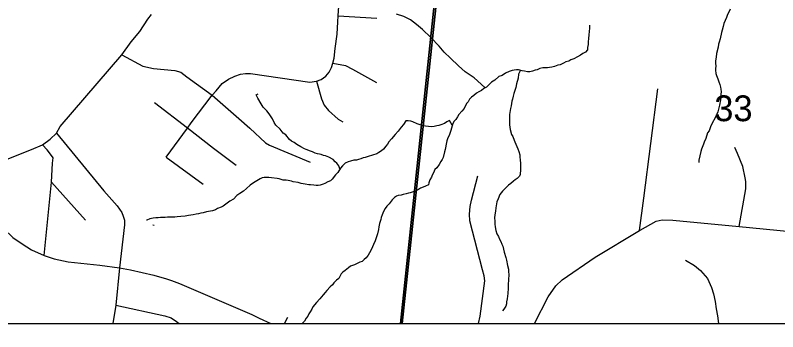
# Model space of a CAD drawing. Extents: x -8.2 to 38.5, y -0.1 to 21.9.
# Drawn here: x 3.122 to 4.362, y 17.376 to 17.891 of the extents above; entities that cross this region are included whole.
import ezdxf

# ---------------------------------------------------------------- set-up
doc = ezdxf.new("R2010")
doc.units = 0
for name, color, linetype in [('Default', 7, 'Continuous'), ('GM_X_Adjacent_County', 7, 'Continuous'), ('GM_X_Adjacent_County_Text', 7, 'Continuous'), ('GM_X_County_Road_Text', 7, 'Continuous'), ('GM_X_Minor_River', 7, 'Continuous'), ('GM_X_Township_Subdivision_Text', 7, 'Continuous'), ('GM_X_Township_Text', 7, 'Continuous')]:
    doc.layers.add(name, color=color, linetype=linetype)

msp = doc.modelspace()

# ---------------------------------------------------------------- linework, layer by layer
at = {"layer": 'Default'}
for points in [[(3.7486, 17.3899), (3.8184, 18.0516), (3.8435, 18.2895), (3.8449, 18.303), (3.8472, 18.3279), (3.8854, 18.7517), (3.9289, 19.2353), (3.9436, 19.3979), (3.9961, 19.9817), (4.0302, 20.3597), (4.0404, 20.4649), (4.0467, 20.5533), (4.0665, 20.7635), (4.0666, 20.7645), (2.1634, 20.7645), (2.1634, 15.4317)], [(8.9634, 15.3136), (8.9634, 20.7535), (8.8842, 20.7645), (4.0666, 20.7645), (4.0665, 20.7635), (4.0467, 20.5533), (4.0404, 20.4649), (4.0302, 20.3597), (3.9961, 19.9817), (3.9436, 19.3979), (3.9289, 19.2353), (3.8854, 18.7517), (3.8472, 18.3279), (3.8449, 18.303), (3.8435, 18.2895), (3.8184, 18.0516), (3.7486, 17.3899)]]:
    msp.add_lwpolyline(points, dxfattribs=at)
at = {"layer": 'GM_X_Adjacent_County'}
msp.add_lwpolyline([(2.2499, 17.3899), (5.0356, 17.3899), (5.0356, 16.67), (2.2499, 16.67)], close=True, dxfattribs=at)
at = {"layer": 'GM_X_Adjacent_County_Text'}
for points in [[(2.8722, 17.3899), (2.7354, 17.4046), (2.8373, 18.4024), (3.8483, 18.3005), (3.7513, 17.3899)], [(3.7513, 17.3899), (3.8483, 18.3005), (4.8395, 18.1926), (4.7544, 17.3899)]]:
    msp.add_lwpolyline(points, dxfattribs=at)
at = {"layer": 'GM_X_Minor_River'}
for points in [[(4.2846, 17.9006), (4.2798, 17.8904), (4.2785, 17.887), (4.2745, 17.8772), (4.2732, 17.8723), (4.2719, 17.8667), (4.2706, 17.8625), (4.2685, 17.8523), (4.2668, 17.847), (4.2659, 17.8436), (4.265, 17.8387), (4.2625, 17.8288), (4.2619, 17.8224), (4.261, 17.8167), (4.2609, 17.8129), (4.2612, 17.8079), (4.2607, 17.8045), (4.261, 17.8015), (4.2616, 17.7961), (4.2627, 17.7926), (4.2644, 17.7873), (4.2662, 17.7826), (4.268, 17.7784), (4.269, 17.7738), (4.2697, 17.7704), (4.2699, 17.7665), (4.2695, 17.7627), (4.2693, 17.7567), (4.2688, 17.7532), (4.2674, 17.7445), (4.2645, 17.7336), (4.2608, 17.7249), (4.2548, 17.7144), (4.2528, 17.7095), (4.2503, 17.7031), (4.2476, 17.6998), (4.2451, 17.6903), (4.2422, 17.6843), (4.2414, 17.6813), (4.2381, 17.6734), (4.2369, 17.6696), (4.2352, 17.6624), (4.2338, 17.6552), (4.2335, 17.6513)], [(3.8859, 17.7726), (3.8795, 17.7789), (3.868, 17.7891), (3.8537, 17.7986), (3.843, 17.8087), (3.8296, 17.8209), (3.8196, 17.8306), (3.8114, 17.8403), (3.7977, 17.8547), (3.784, 17.8676), (3.7743, 17.8758), (3.7646, 17.8833), (3.7537, 17.8889), (3.742, 17.8926)], [(4.0561, 17.8746), (4.0556, 17.8693), (4.0551, 17.8651), (4.0549, 17.8582), (4.0544, 17.8533), (4.0538, 17.8472), (4.0537, 17.8434), (4.0528, 17.8381), (4.0524, 17.8347), (4.0492, 17.831), (4.045, 17.8284), (4.0411, 17.8259), (4.0365, 17.8233), (4.0303, 17.8197), (4.0257, 17.8183), (4.0222, 17.8161), (4.0176, 17.8151), (4.0134, 17.8129), (4.0084, 17.8104), (4.0045, 17.8094), (3.9992, 17.8076), (3.9946, 17.8062), (3.9907, 17.8056), (3.9873, 17.8053), (3.9839, 17.8054), (3.9801, 17.8051), (3.9751, 17.8041), (3.9705, 17.8023), (3.9674, 17.8013), (3.9632, 17.7999), (3.9586, 17.7988), (3.9552, 17.7986), (3.9499, 17.7998), (3.9465, 17.8007), (3.9404, 17.802), (3.937, 17.8021), (3.9332, 17.8018), (3.9301, 17.8008), (3.9252, 17.7994), (3.9194, 17.7969), (3.9136, 17.7929), (3.9086, 17.7911), (3.902, 17.7852), (3.8965, 17.7819), (3.8884, 17.7741), (3.8841, 17.7716), (3.8802, 17.7683), (3.8756, 17.7665), (3.8721, 17.7639), (3.8678, 17.7606), (3.8639, 17.7577), (3.8608, 17.7543), (3.8584, 17.7502), (3.8557, 17.7472), (3.852, 17.7394), (3.8481, 17.7349), (3.8434, 17.7293), (3.8414, 17.7256), (3.8386, 17.7211), (3.8355, 17.7189), (3.8335, 17.7147), (3.8302, 17.7034), (3.8277, 17.6955), (3.8256, 17.6913), (3.824, 17.6868), (3.8235, 17.6838), (3.8209, 17.6724), (3.8201, 17.669), (3.8176, 17.6596), (3.8163, 17.6566), (3.8143, 17.6532), (3.8116, 17.6483), (3.8076, 17.6427), (3.8045, 17.6401), (3.802, 17.6345), (3.8, 17.6307), (3.7988, 17.6277), (3.7964, 17.6232), (3.7944, 17.6183), (3.7939, 17.6153), (3.7889, 17.6131), (3.7855, 17.6113), (3.7812, 17.6099), (3.7762, 17.6066), (3.7704, 17.6041), (3.7643, 17.6024), (3.7612, 17.6017), (3.7574, 17.6007), (3.7528, 17.5993), (3.7494, 17.5986), (3.7448, 17.598), (3.7417, 17.5966), (3.7386, 17.5947), (3.7347, 17.591), (3.73, 17.5843), (3.7261, 17.5806), (3.7237, 17.5769), (3.7209, 17.5716), (3.7184, 17.5664), (3.7168, 17.5622), (3.7163, 17.5588)], [(3.9435, 17.8015), (3.9402, 17.7948), (3.9397, 17.7887), (3.9372, 17.7792), (3.9359, 17.7736), (3.9326, 17.7634), (3.9317, 17.7592), (3.9308, 17.7543), (3.9296, 17.7513), (3.9286, 17.7437), (3.9273, 17.7392), (3.9259, 17.7297), (3.9257, 17.7202), (3.9259, 17.7125), (3.9265, 17.7091), (3.9268, 17.7049), (3.9292, 17.6968), (3.931, 17.6937), (3.9335, 17.6879), (3.9346, 17.6849), (3.936, 17.6814), (3.9378, 17.6775), (3.9393, 17.6737), (3.9407, 17.6695), (3.9424, 17.6637), (3.9427, 17.6603), (3.9429, 17.6557), (3.9435, 17.6496), (3.9438, 17.6458), (3.9437, 17.6401), (3.9431, 17.6321), (3.9422, 17.6291), (3.9383, 17.6254), (3.9352, 17.6235), (3.9321, 17.6213), (3.9278, 17.6173), (3.9243, 17.6147), (3.9181, 17.6088), (3.9146, 17.6047), (3.9099, 17.5995), (3.9074, 17.5927), (3.9054, 17.5874), (3.9036, 17.578), (3.9027, 17.5726), (3.9021, 17.5662), (3.9016, 17.5613), (3.9018, 17.5563), (3.9017, 17.5513), (3.9023, 17.5468), (3.9037, 17.541), (3.9051, 17.5356), (3.9076, 17.531), (3.9094, 17.5271), (3.9116, 17.5229), (3.9134, 17.5187), (3.9148, 17.5156), (3.9172, 17.5056), (3.9196, 17.4971), (3.9207, 17.4925), (3.9223, 17.4841), (3.9241, 17.478), (3.9243, 17.473), (3.9246, 17.47), (3.9243, 17.4601), (3.9238, 17.4536), (3.9236, 17.4471), (3.923, 17.4384), (3.922, 17.4297), (3.9211, 17.4251), (3.9206, 17.4217), (3.9198, 17.4179), (3.9166, 17.4131), (3.9142, 17.4103)], [(3.65, 17.641), (3.648, 17.646), (3.645, 17.6503), (3.6421, 17.6527), (3.6387, 17.6562), (3.6316, 17.6602), (3.6264, 17.6622), (3.6233, 17.6631), (3.6196, 17.6643), (3.6165, 17.6648), (3.6135, 17.6656), (3.6097, 17.6665), (3.6052, 17.6689), (3.6018, 17.6698), (3.5951, 17.6726), (3.5921, 17.6739), (3.5861, 17.6767), (3.5797, 17.6807), (3.5756, 17.6838), (3.5711, 17.6863), (3.5678, 17.689), (3.5619, 17.6964), (3.5574, 17.6992), (3.5526, 17.7054), (3.5456, 17.7121), (3.543, 17.7167), (3.5401, 17.7222), (3.5347, 17.7307), (3.531, 17.7354), (3.5276, 17.7385), (3.5251, 17.7416), (3.5218, 17.7467), (3.5163, 17.756), (3.5134, 17.7614), (3.5169, 17.7632)], [(3.8327, 17.712), (3.8279, 17.7195), (3.8237, 17.7177), (3.8202, 17.7147), (3.8141, 17.7126), (3.8106, 17.7116), (3.8075, 17.7109), (3.8033, 17.7099), (3.7984, 17.7092), (3.7847, 17.7111), (3.7787, 17.7132), (3.7757, 17.7141), (3.7685, 17.7173), (3.7652, 17.7185), (3.761, 17.7194), (3.7572, 17.7191), (3.7532, 17.7135), (3.7493, 17.7087), (3.7446, 17.7024), (3.7395, 17.6968), (3.734, 17.6901), (3.7293, 17.6853), (3.7273, 17.6811), (3.7245, 17.6782), (3.7206, 17.6729), (3.7175, 17.6704), (3.7132, 17.6678), (3.7097, 17.6656), (3.7028, 17.6632), (3.6959, 17.6611), (3.6909, 17.6597), (3.6879, 17.659), (3.684, 17.6572), (3.6802, 17.6566), (3.6771, 17.6555), (3.6726, 17.6552), (3.6672, 17.6535), (3.6634, 17.6524), (3.6584, 17.6503), (3.654, 17.6459), (3.6509, 17.6425), (3.6465, 17.6354), (3.6426, 17.6317), (3.6375, 17.6242), (3.6344, 17.6216), (3.6305, 17.6199), (3.6255, 17.6173), (3.6224, 17.6163), (3.6175, 17.6149), (3.6144, 17.6142), (3.611, 17.6139), (3.6072, 17.6144), (3.6023, 17.6153), (3.5992, 17.6154), (3.5935, 17.6163), (3.5871, 17.6176), (3.5818, 17.6189), (3.5739, 17.6203), (3.5709, 17.6211), (3.5656, 17.622), (3.5625, 17.6225), (3.5576, 17.623), (3.5512, 17.6247), (3.5478, 17.6256), (3.5387, 17.6266), (3.5345, 17.6271), (3.5307, 17.6272), (3.5265, 17.6269), (3.5235, 17.6263), (3.5204, 17.6252), (3.5173, 17.6234), (3.5123, 17.6201), (3.5092, 17.6183), (3.5041, 17.6146), (3.4979, 17.6091), (3.4928, 17.605), (3.487, 17.601), (3.4824, 17.5977), (3.4769, 17.5921), (3.4707, 17.5885), (3.4599, 17.5804), (3.4568, 17.579), (3.451, 17.5765), (3.4475, 17.5747), (3.4425, 17.5729), (3.433, 17.5713), (3.4272, 17.5695), (3.4234, 17.5689), (3.4196, 17.5679), (3.4162, 17.5676), (3.4112, 17.5666), (3.4036, 17.5656), (3.3982, 17.5643), (3.391, 17.5637), (3.3849, 17.5631), (3.3814, 17.5628), (3.3772, 17.5626), (3.3734, 17.5627), (3.3692, 17.5624), (3.3654, 17.5621), (3.3613, 17.5622)], [(3.3613, 17.5622), (3.3578, 17.562), (3.354, 17.5617), (3.3506, 17.5614), (3.346, 17.5611), (3.3406, 17.5598), (3.3357, 17.558), (3.3353, 17.5579)], [(3.7163, 17.5588), (3.7143, 17.5524), (3.7134, 17.5471), (3.7125, 17.5425), (3.7108, 17.5357), (3.7095, 17.5308), (3.7074, 17.5244), (3.7046, 17.5184), (3.701, 17.5105), (3.6981, 17.5045), (3.6958, 17.5007), (3.6926, 17.4966), (3.6891, 17.4941), (3.686, 17.4907), (3.6821, 17.4893), (3.6737, 17.4853), (3.6702, 17.4839), (3.6671, 17.4832), (3.6636, 17.4803), (3.6586, 17.4762), (3.6547, 17.4733), (3.652, 17.4703), (3.648, 17.4632), (3.6441, 17.4603), (3.6402, 17.4558), (3.6378, 17.4528), (3.6343, 17.4495), (3.6288, 17.4436), (3.626, 17.4402), (3.6225, 17.4365), (3.6201, 17.4331), (3.617, 17.4298), (3.6119, 17.4242), (3.606, 17.4168), (3.6044, 17.4134), (3.6016, 17.4089), (3.5996, 17.4055), (3.5976, 17.4018), (3.5949, 17.3984), (3.5921, 17.3939), (3.5889, 17.3902), (3.5883, 17.3899)], [(3.3454, 17.5501), (3.3476, 17.5497)], [(4.2119, 17.4928), (4.2265, 17.4841), (4.2365, 17.4758), (4.248, 17.463), (4.2545, 17.4484), (4.2576, 17.4381), (4.2604, 17.4258), (4.262, 17.4136), (4.264, 17.4025), (4.2659, 17.3899)]]:
    msp.add_lwpolyline(points, dxfattribs=at)
at = {"layer": 'GM_X_Township_Subdivision_Text'}
for p, q in [((3.6471, 17.8897), (3.71, 17.886)), ((3.367, 17.6599), (3.4272, 17.6161)), ((3.181, 17.6197), (3.2362, 17.558)), ((3.5598, 17.3899), (3.5654, 17.3999))]:
    msp.add_line(p, q, dxfattribs=at)
for points in [[(3.6463, 17.8799), (3.6471, 17.8897), (3.6502, 17.9373), (3.6551, 18.0086)], [(3.367, 17.6599), (3.4018, 17.7072), (3.4079, 17.7157), (3.4422, 17.761), (3.4484, 17.7678), (3.4585, 17.78), (3.4685, 17.787), (3.479, 17.792), (3.4881, 17.795), (3.4963, 17.7959), (3.5046, 17.7961), (3.6012, 17.7819), (3.6119, 17.7835), (3.6195, 17.7866), (3.6268, 17.7919), (3.6323, 17.7984), (3.6364, 17.8059), (3.6385, 17.813), (3.6403, 17.8208), (3.6419, 17.8367), (3.6456, 17.8602), (3.6463, 17.8799)], [(3.2952, 17.8264), (3.3292, 17.8082), (3.3464, 17.8045), (3.3811, 17.8012), (3.3913, 17.7982), (3.4008, 17.7908), (3.4422, 17.761), (3.4855, 17.7228), (3.5032, 17.7071), (3.5286, 17.6835), (3.5355, 17.6797), (3.6014, 17.6521)], [(3.6385, 17.813), (3.6589, 17.809), (3.6704, 17.8029), (3.7094, 17.7814)], [(3.6119, 17.7835), (3.6201, 17.7551), (3.6241, 17.7448), (3.6313, 17.7358), (3.647, 17.7217), (3.6549, 17.7178)], [(4.1373, 17.5411), (4.144, 17.5934), (4.1671, 17.7711)], [(3.4813, 17.6465), (3.4442, 17.674), (3.4018, 17.7072), (3.3485, 17.7485)], [(3.1887, 17.6993), (3.2658, 17.6054), (3.2874, 17.581), (3.295, 17.5702), (3.2975, 17.5643), (3.2997, 17.5576), (3.2993, 17.5501), (3.2912, 17.4805), (3.2854, 17.4197), (3.2807, 17.3899)], [(3.1686, 17.5004), (3.181, 17.6197), (3.1826, 17.6503), (3.1835, 17.6588), (3.1792, 17.665), (3.1735, 17.6721), (3.1663, 17.6803)], [(4.2991, 17.5474), (4.31, 17.6087), (4.3104, 17.613), (4.31, 17.6205), (4.3089, 17.6268), (4.3051, 17.6451), (4.2968, 17.6663), (4.292, 17.6758)], [(3.8751, 17.3899), (3.8778, 17.4015), (3.8854, 17.4591), (3.8844, 17.4675), (3.8817, 17.477), (3.861, 17.5566), (3.8609, 17.5676), (3.862, 17.5801), (3.8638, 17.59), (3.8743, 17.6296)], [(3.2854, 17.4197), (3.3651, 17.4021), (3.3752, 17.3988), (3.3841, 17.3932), (3.3883, 17.3899)]]:
    msp.add_lwpolyline(points, dxfattribs=at)
at = {"layer": 'GM_X_Township_Text'}
msp.add_line((3.5183, 17.3987), (3.5375, 17.3899), dxfattribs=at)
for points in [[(3.0359, 17.628), (3.148, 17.6724), (3.1663, 17.6803), (3.1786, 17.6894), (3.1887, 17.6993), (3.1948, 17.7098), (3.2952, 17.8264), (3.3102, 17.8475), (3.3243, 17.8643), (3.3377, 17.8845), (3.3432, 17.8918)], [(3.0842, 17.5653), (3.0888, 17.5593), (3.0958, 17.5517), (3.1033, 17.5436), (3.1181, 17.5298), (3.1331, 17.5194), (3.1481, 17.5097), (3.1686, 17.5004), (3.1853, 17.495), (3.2081, 17.4898), (3.2592, 17.4845), (3.2912, 17.4805), (3.3093, 17.4768), (3.347, 17.4682), (3.3677, 17.4624), (3.376, 17.4595), (3.3891, 17.4547), (3.5064, 17.4042), (3.5183, 17.3987)], [(3.9666, 17.3899), (3.9888, 17.4333), (4.0009, 17.4513), (4.0113, 17.461), (4.0652, 17.4975), (4.1373, 17.5411), (4.1381, 17.5416), (4.1642, 17.5559), (4.1741, 17.5584), (4.1912, 17.5576), (4.2991, 17.5474), (4.4052, 17.5374), (4.4793, 17.5303)]]:
    msp.add_lwpolyline(points, dxfattribs=at)

# ---------------------------------------------------------------- texts
at = {"layer": 'GM_X_County_Road_Text'}
msp.add_text('33', height=0.04186, rotation=0, dxfattribs=at).set_placement((4.2588, 17.7186))

doc.saveas('drawing.dxf')
